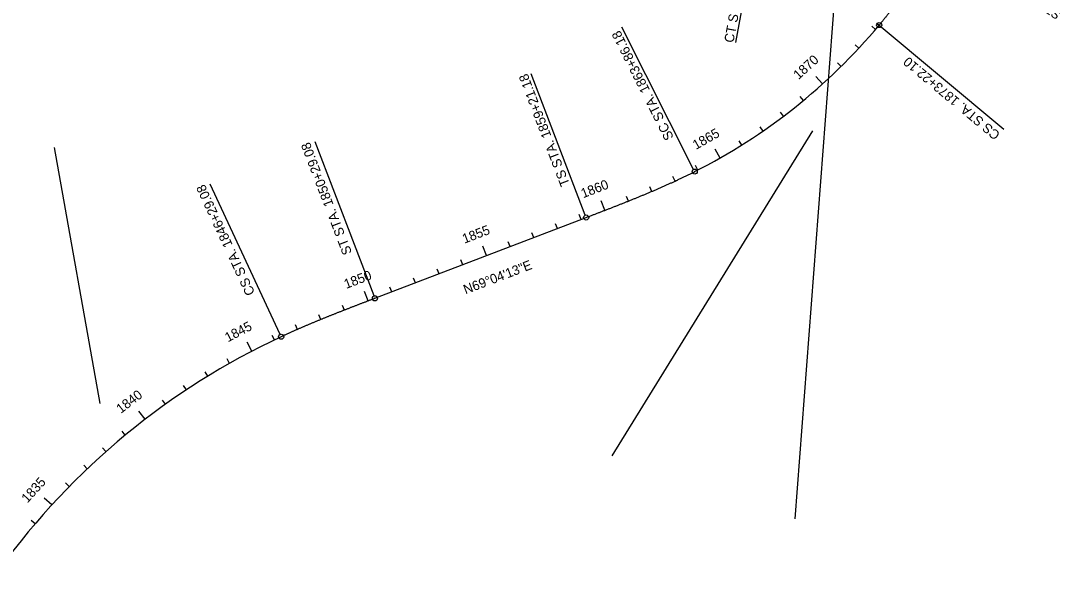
# Model space of a CAD drawing. Extents: x 1280727 to 1452510, y 526233 to 601451.
# Drawn here: x 1437617 to 1441688, y 588837 to 590996 of the extents above; entities that cross this region are included whole.
import ezdxf

# ---------------------------------------------------------------- set-up
doc = ezdxf.new("R2010")
doc.units = 0
for name, color, linetype in [('Level 63', 7, 'Continuous'), ('RW_X_CL', 7, 'Continuous'), ('RW_X_CL_500_Stations', 7, 'Continuous'), ('SH_Text', 7, 'Continuous')]:
    doc.layers.add(name, color=color, linetype=linetype)

msp = doc.modelspace()

# ---------------------------------------------------------------- linework, layer by layer
at = {"layer": 'Level 63'}
for p, q in [((1440868.2, 591608.6), (1440672.4, 589032.5)), ((1440742.2, 590562.2), (1439949.3, 589280.6)), ((1437931.4, 589487.2), (1437751.5, 590496.6))]:
    msp.add_line(p, q, dxfattribs=at)
at = {"layer": 'RW_X_CL'}
msp.add_line((1439015.3, 589901.7), (1439848.6, 590220.4), dxfattribs=at)
for centre, radius, start, end in [((1439245.5, 592447.7), 2291.8, 296.7423, 320.1404), ((1439852.7, 587152.3), 2864.8, 114.9298, 143.9708)]:
    msp.add_arc(centre, radius, start, end, dxfattribs=at)
for points in [[(1441277.9, 591354.9), (1441274.4, 591349.7), (1441270.8, 591344.5), (1441267.3, 591339.3), (1441263.8, 591334.1), (1441260.3, 591328.9), (1441256.8, 591323.7), (1441253.2, 591318.5), (1441249.7, 591313.3), (1441246.2, 591308.1), (1441242.7, 591302.9), (1441239.1, 591297.7), (1441235.6, 591292.5), (1441232.1, 591287.3), (1441228.5, 591282.1), (1441225, 591276.9), (1441221.5, 591271.7), (1441217.9, 591266.5), (1441214.4, 591261.3), (1441210.8, 591256.1), (1441207.3, 591251), (1441203.7, 591245.8), (1441200.1, 591240.6), (1441196.6, 591235.4), (1441193, 591230.3), (1441189.4, 591225.1), (1441185.8, 591219.9), (1441182.3, 591214.8), (1441178.7, 591209.6), (1441175.1, 591204.5), (1441171.5, 591199.3), (1441167.9, 591194.2), (1441164.2, 591189), (1441160.6, 591183.9), (1441157, 591178.8), (1441153.4, 591173.6), (1441149.7, 591168.5), (1441146.1, 591163.4), (1441142.4, 591158.3), (1441138.8, 591153.2), (1441135.1, 591148.1), (1441131.4, 591143), (1441127.7, 591137.9), (1441124.1, 591132.8), (1441120.4, 591127.7), (1441116.7, 591122.6), (1441112.9, 591117.6), (1441109.2, 591112.5), (1441105.5, 591107.5), (1441101.7, 591102.4), (1441098, 591097.4), (1441094.2, 591092.3), (1441090.5, 591087.3), (1441086.7, 591082.3), (1441082.9, 591077.3), (1441079.1, 591072.3), (1441075.3, 591067.3), (1441071.5, 591062.3), (1441067.6, 591057.3), (1441063.8, 591052.3), (1441059.9, 591047.4), (1441056.1, 591042.4), (1441052.2, 591037.5), (1441048.3, 591032.5), (1441044.4, 591027.6), (1441040.5, 591022.7), (1441036.6, 591017.8), (1441032.7, 591012.9), (1441028.7, 591008), (1441024.8, 591003.1), (1441020.8, 590998.2), (1441016.8, 590993.4), (1441012.8, 590988.5), (1441008.8, 590983.7), (1441004.8, 590978.8)], [(1439848.6, 590220.4), (1439854.4, 590222.6), (1439860.3, 590224.9), (1439866.2, 590227.1), (1439872, 590229.4), (1439877.9, 590231.6), (1439883.8, 590233.9), (1439889.6, 590236.1), (1439895.5, 590238.4), (1439901.4, 590240.6), (1439907.2, 590242.9), (1439913.1, 590245.1), (1439919, 590247.4), (1439924.8, 590249.6), (1439930.7, 590251.9), (1439936.5, 590254.2), (1439942.4, 590256.4), (1439948.3, 590258.7), (1439954.1, 590261), (1439960, 590263.3), (1439965.8, 590265.6), (1439971.7, 590267.9), (1439977.5, 590270.1), (1439983.4, 590272.4), (1439989.2, 590274.7), (1439995.1, 590277.1), (1440000.9, 590279.4), (1440006.7, 590281.7), (1440012.6, 590284), (1440018.4, 590286.4), (1440024.2, 590288.7), (1440030.1, 590291), (1440035.9, 590293.4), (1440041.7, 590295.8), (1440047.5, 590298.1), (1440053.4, 590300.5), (1440059.2, 590302.9), (1440065, 590305.3), (1440070.8, 590307.7), (1440076.6, 590310.1), (1440082.4, 590312.5), (1440088.2, 590314.9), (1440094, 590317.3), (1440099.8, 590319.8), (1440105.6, 590322.2), (1440111.4, 590324.7), (1440117.1, 590327.1), (1440122.9, 590329.6), (1440128.7, 590332.1), (1440134.5, 590334.6), (1440140.2, 590337.1), (1440146, 590339.6), (1440151.7, 590342.2), (1440157.5, 590344.7), (1440163.2, 590347.3), (1440168.9, 590349.8), (1440174.7, 590352.4), (1440180.4, 590355), (1440186.1, 590357.6), (1440191.8, 590360.2), (1440197.6, 590362.8), (1440203.3, 590365.5), (1440209, 590368.1), (1440214.6, 590370.8), (1440220.3, 590373.5), (1440226, 590376.1), (1440231.7, 590378.8), (1440237.3, 590381.6), (1440243, 590384.3), (1440248.7, 590387), (1440254.3, 590389.8), (1440259.9, 590392.6), (1440265.6, 590395.4), (1440271.2, 590398.2), (1440276.8, 590401)], [(1439015.3, 589901.7), (1439010.3, 589899.8), (1439005.2, 589897.8), (1439000.2, 589895.9), (1438995.1, 589894), (1438990.1, 589892), (1438985, 589890.1), (1438980, 589888.2), (1438974.9, 589886.2), (1438969.9, 589884.3), (1438964.8, 589882.4), (1438959.8, 589880.4), (1438954.7, 589878.5), (1438949.7, 589876.5), (1438944.7, 589874.6), (1438939.6, 589872.7), (1438934.6, 589870.7), (1438929.5, 589868.8), (1438924.5, 589866.8), (1438919.4, 589864.9), (1438914.4, 589862.9), (1438909.4, 589860.9), (1438904.3, 589859), (1438899.3, 589857), (1438894.3, 589855.1), (1438889.2, 589853.1), (1438884.2, 589851.1), (1438879.2, 589849.1), (1438874.1, 589847.2), (1438869.1, 589845.2), (1438864.1, 589843.2), (1438859, 589841.2), (1438854, 589839.2), (1438849, 589837.2), (1438844, 589835.2), (1438839, 589833.2), (1438833.9, 589831.2), (1438828.9, 589829.2), (1438823.9, 589827.1), (1438818.9, 589825.1), (1438813.9, 589823.1), (1438808.9, 589821.1), (1438803.9, 589819), (1438798.9, 589817), (1438793.9, 589814.9), (1438788.9, 589812.9), (1438783.9, 589810.8), (1438778.9, 589808.7), (1438773.9, 589806.6), (1438768.9, 589804.6), (1438763.9, 589802.5), (1438758.9, 589800.4), (1438754, 589798.3), (1438749, 589796.2), (1438744, 589794.1), (1438739, 589791.9), (1438734.1, 589789.8), (1438729.1, 589787.7), (1438724.1, 589785.5), (1438719.2, 589783.4), (1438714.2, 589781.2), (1438709.3, 589779.1), (1438704.3, 589776.9), (1438699.4, 589774.7), (1438694.4, 589772.5), (1438689.5, 589770.3), (1438684.6, 589768.1), (1438679.6, 589765.9), (1438674.7, 589763.7), (1438669.8, 589761.5), (1438664.9, 589759.2), (1438659.9, 589757), (1438655, 589754.7), (1438650.1, 589752.5), (1438645.2, 589750.2)]]:
    msp.add_spline(points, degree=3, dxfattribs=at)
at = {"layer": 'RW_X_CL_500_Stations'}
for p, q in [((1440990.5, 590961.9), (1440975.3, 590974.9)), ((1440924.1, 590887.2), (1440909.4, 590900.9)), ((1440854.4, 590815.5), (1440840.4, 590829.7)), ((1440781.7, 590746.9), (1440754.9, 590776.6)), ((1440706, 590681.5), (1440693.3, 590696.9)), ((1440627.6, 590619.5), (1440615.5, 590635.4)), ((1440546.5, 590560.9), (1440535.2, 590577.4)), ((1440463, 590506), (1440452.4, 590522.9)), ((1440377.1, 590454.7), (1440357.4, 590489.5)), ((1440289.1, 590407.2), (1440280, 590425.1)), ((1440199.2, 590363.6), (1440190.8, 590381.7)), ((1440107.7, 590323.1), (1440099.9, 590341.5)), ((1439922.1, 590248.6), (1439907.7, 590285.9)), ((1440015.3, 590285.1), (1440007.8, 590303.7)), ((1439828.8, 590212.8), (1439821.6, 590231.5)), ((1439735.4, 590177.1), (1439728.2, 590195.8)), ((1439642, 590141.4), (1439634.8, 590160)), ((1439455.2, 590069.9), (1439440.9, 590107.3)), ((1439548.6, 590105.6), (1439541.4, 590124.3)), ((1439361.8, 590034.2), (1439354.6, 590052.9)), ((1439175, 589962.8), (1439167.8, 589981.4)), ((1439268.4, 589998.5), (1439261.2, 590017.2)), ((1439081.6, 589927), (1439074.4, 589945.7)), ((1438988.2, 589891.3), (1438973.9, 589928.7)), ((1438894.9, 589855.3), (1438887.6, 589873.9)), ((1438802, 589818.2), (1438794.4, 589836.7)), ((1438709.9, 589779.3), (1438701.9, 589797.7)), ((1438618.9, 589737.8), (1438610.3, 589755.8)), ((1438529.4, 589693.2), (1438511, 589728.6)), ((1438441.6, 589645.4), (1438431.7, 589662.8)), ((1438355.4, 589594.7), (1438345, 589611.7)), ((1438271.1, 589540.9), (1438260, 589557.6)), ((1438188.7, 589484.3), (1438177.1, 589500.5)), ((1438108.3, 589424.8), (1438084, 589456.5)), ((1438030.1, 589362.5), (1438017.4, 589377.9)), ((1437954.1, 589297.5), (1437940.8, 589312.5)), ((1437880.3, 589230), (1437866.6, 589244.5)), ((1437809, 589159.9), (1437794.8, 589173.9)), ((1437740.2, 589087.3), (1437710.7, 589114.3)), ((1437674, 589012.4), (1437658.8, 589025.4))]:
    msp.add_line(p, q, dxfattribs=at)
at = {"layer": 'SH_Text'}
for p, q in [((1440527.1, 591395.2), (1440438, 590909.5)), ((1440272.3, 590409.9), (1439989.6, 590971)), ((1440997.1, 590985.2), (1441496.4, 590568.4)), ((1439845, 590229.7), (1439632.1, 590786.4)), ((1439011.7, 589911), (1438779.4, 590518.6)), ((1438641, 589759.3), (1438365.4, 590352.1))]:
    msp.add_line(p, q, dxfattribs=at)
for centre in [(1441004.8, 590978.8), (1440276.8, 590401), (1439848.6, 590220.4), (1439015.3, 589901.7), (1438645.2, 589750.2)]:
    msp.add_circle(centre, 10, dxfattribs=at)

# ---------------------------------------------------------------- texts
at = {"layer": 'RW_X_CL_500_Stations'}
for s, rotation, p in [('1870', 42.0879, (1440686.7, 590762.1)), ('1865', 29.5879, (1440282, 590486.6)), ('1860', 21.0968, (1439836.7, 590296)), ('1855', 20.9298, (1439368.4, 590117)), ('1850', 20.9509, (1438901.8, 589938.5)), ('1845', 27.5113, (1438435.1, 589728.1)), ('1840', 37.5113, (1438012.9, 589446.1)), ('1835', 47.5113, (1437644.1, 589092.9))]:
    msp.add_text(s, height=37.5, rotation=rotation, dxfattribs=at).set_placement(p)
at = {"layer": 'SH_Text'}
for s, rotation, p in [('CT STA. 4759+48.76', 79.6079, (1440429.7, 590907.1)), ('ST STA. 1877+87.10', 145.9529, (1441790.8, 590985.4)), ('SC STA. 1863+86.18', 116.7423, (1440195.1, 590536.1)), ('CS STA. 1873+22.10', 140.1404, (1441485, 590551.5)), ('TS STA. 1859+21.18', 110.9298, (1439784.6, 590351.8)), ('ST STA. 1850+29.08', 110.9298, (1438925.2, 590081.4)), ('CS STA. 1846+29.08', 114.9298, (1438542.8, 589923.1)), ('N69°04\'13"E', 20.9298, (1439372.9, 589917.1))]:
    msp.add_text(s, height=37.5, rotation=rotation, dxfattribs=at).set_placement(p)

doc.saveas('drawing.dxf')
